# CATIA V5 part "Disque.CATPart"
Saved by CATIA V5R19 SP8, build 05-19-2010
Part number: Disque
Bounding box of the stored display mesh (mm): x -11 to -5, y -20.494 to 20.494, z -20.494 to 20.494
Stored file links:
  C:\Users\ThinkMotion\Desktop\EU_thinkMotion\iao\IAO_MMS_Groupe3\ecartoux\projet_IAO_ecartoux\projet_IAO_ecartoux\griffe_d'une_camera_ecartoux\Disque.CATPart
  C:\Users\ThinkMotion\Desktop\EU_thinkMotion\iao\IAO_MMS_Groupe3\ecartoux\projet_IAO_ecartoux\projet_IAO_ecartoux\griffe_d'une_camera_ecartoux\Mecanisme_a_coulisse_et_leviers_de_la_griffe_d'un_camera_ecartoux.CATProduct
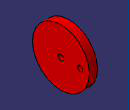
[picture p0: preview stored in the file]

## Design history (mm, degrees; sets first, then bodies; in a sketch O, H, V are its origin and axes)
Set1
  Plane1 "Plan.2": linked copy from another document
  Line1: linked copy from another document
  Point1: linked copy from another document
  Plane2 "Plan.1": linked copy from another document
  Point2: linked copy from another document
Body1 (main body)
  Sketch1 on Plane1, origin (0, 0, 0), H (1, 0, 0), V (0, 1, 0)
    line L1 (-11, 2) -> (-5, 2)
    line L2 (-5, 2) -> (-5, 20.5)
    line L3 (-5, 20.5) -> (-11, 20.5)
    line L4 (-11, 20.5) -> (-11, 2)
    reference projected line E1 (11, 0) -> (-11, 0) from Line1
    reference projected point E2 (0, 0) from Point1
    distance L4 L2 = 6
    distance L3 L1 = 18.5
    distance L1 E1 = 2
    distance L2 E2 = 5
    horizontal: L1 H, L3 H
    vertical: L2 V, L4 V
  Shaft1: profile Sketch1, axis Line1, angle 360
  Sketch2 on Plane2, origin (-8, 0, 0), H (0, 1, 0), V (0, 0, 1)
    circle A1 centre (14, 0) radius 2
    point P1 (14, 0)
    reference projected point E1 (14, 0) from Point2
    radius A1 = 2
    coincidence: P1 E1
  Pocket1: profile Sketch2, direction (-1, 0, 0), length 3, mirrored extent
